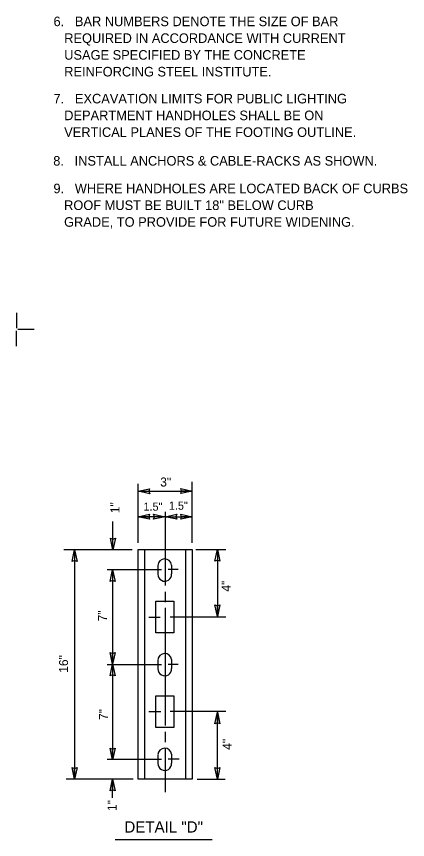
# Model space of a CAD drawing. Extents: x 19188 to 19495, y 20866 to 21061.
# Drawn here: x 19246.2 to 19280.4, y 20889.5 to 20961.5 of the extents above; entities that cross this region are included whole.
import ezdxf

# ---------------------------------------------------------------- set-up
doc = ezdxf.new("R2010")
doc.units = 0
doc.layers.add('G-ANNO-NOTE', color=7, linetype='Continuous')

msp = doc.modelspace()

# ---------------------------------------------------------------- linework, layer by layer
at = {"layer": 'G-ANNO-NOTE'}
for p, q in [((19246.175, 20935.559), (19246.175, 20934.208)), ((19246.175, 20935.559), (19246.175, 20934.208)), ((19246.175, 20932.625), (19246.175, 20933.971)), ((19246.175, 20932.625), (19246.175, 20933.971)), ((19247.715, 20934.094), (19246.305, 20934.094)), ((19247.715, 20934.094), (19246.305, 20934.094)), ((19261.529, 20915.424), (19261.529, 20920.761)), ((19256.799, 20915.424), (19256.799, 20920.584)), ((19256.799, 20919.942), (19261.546, 20919.942)), ((19256.799, 20919.942), (19257.735, 20919.942)), ((19261.546, 20919.942), (19260.61, 20919.942)), ((19254.602, 20914.807), (19254.602, 20917.298)), ((19259.164, 20917.708), (19256.793, 20917.708)), ((19256.793, 20917.708), (19257.729, 20917.708)), ((19259.164, 20917.708), (19258.228, 20917.708)), ((19259.164, 20917.708), (19261.546, 20917.708)), ((19259.164, 20917.708), (19260.1, 20917.708)), ((19261.546, 20917.708), (19260.61, 20917.708)), ((19254.602, 20914.807), (19254.602, 20915.743)), ((19256.296, 20914.807), (19250.307, 20914.807)), ((19251.258, 20914.807), (19251.258, 20894.757)), ((19251.258, 20914.807), (19251.258, 20913.87)), ((19256.799, 20914.833), (19261.529, 20914.833)), ((19256.799, 20894.757), (19256.799, 20914.833)), ((19257.39, 20894.757), (19257.39, 20914.833)), ((19260.938, 20914.833), (19260.938, 20894.757)), ((19261.529, 20914.833), (19261.529, 20894.757)), ((19261.856, 20914.839), (19264.487, 20914.839)), ((19263.74, 20914.839), (19263.74, 20908.99)), ((19263.74, 20914.839), (19263.74, 20913.903)), ((19254.101, 20913.097), (19258.841, 20913.098)), ((19254.58, 20913.073), (19254.581, 20904.805)), ((19254.58, 20913.073), (19254.581, 20912.137)), ((19258.539, 20913.446), (19258.539, 20912.658)), ((19260.303, 20913.098), (19259.437, 20913.098)), ((19259.721, 20913.482), (19259.721, 20912.713)), ((19258.361, 20910.314), (19259.938, 20910.314)), ((19258.361, 20907.555), (19258.361, 20910.314)), ((19259.938, 20910.314), (19259.938, 20907.555)), ((19263.74, 20908.99), (19263.74, 20909.926)), ((19257.746, 20908.934), (19258.733, 20908.934)), ((19264.487, 20908.935), (19259.6, 20908.934)), ((19259.938, 20907.555), (19258.361, 20907.555)), ((19254.581, 20904.805), (19254.581, 20905.742)), ((19258.539, 20905.169), (19258.539, 20904.38)), ((19259.721, 20905.205), (19259.721, 20904.436)), ((19254.102, 20904.775), (19258.841, 20904.775)), ((19254.581, 20904.805), (19254.582, 20896.437)), ((19254.581, 20904.805), (19254.581, 20903.869)), ((19260.304, 20904.775), (19259.437, 20904.775)), ((19258.361, 20902.037), (19259.938, 20902.037)), ((19258.361, 20899.277), (19258.361, 20902.037)), ((19259.938, 20902.037), (19259.938, 20899.277)), ((19257.747, 20900.657), (19258.787, 20900.657)), ((19264.488, 20900.657), (19259.6, 20900.657)), ((19263.74, 20900.621), (19263.74, 20899.685)), ((19263.74, 20894.757), (19263.74, 20900.621)), ((19259.938, 20899.277), (19258.361, 20899.277)), ((19254.582, 20896.437), (19254.582, 20897.373)), ((19254.102, 20896.497), (19258.841, 20896.497)), ((19258.539, 20896.891), (19258.539, 20896.103)), ((19260.409, 20896.497), (19259.437, 20896.497)), ((19259.721, 20896.927), (19259.721, 20896.158)), ((19251.258, 20894.757), (19251.258, 20895.693)), ((19263.74, 20894.757), (19263.74, 20895.693)), ((19256.387, 20894.749), (19250.519, 20894.749)), ((19254.582, 20893.11), (19254.582, 20894.749)), ((19254.582, 20894.749), (19254.582, 20893.813)), ((19261.529, 20894.757), (19256.799, 20894.757)), ((19261.969, 20894.749), (19264.419, 20894.749)), ((19254.787, 20889.468), (19263.277, 20889.468))]:
    msp.add_line(p, q, dxfattribs=at)
for points in [[(19257.735, 20919.942), (19257.817, 20919.718), (19256.799, 20919.942), (19257.815, 20920.156), (19257.735, 20919.942)], [(19260.61, 20919.942), (19260.528, 20920.166), (19261.546, 20919.942), (19260.53, 20919.728), (19260.61, 20919.942)], [(19257.73, 20917.708), (19257.811, 20917.484), (19256.793, 20917.708), (19257.809, 20917.922), (19257.73, 20917.708)], [(19258.227, 20917.708), (19258.145, 20917.932), (19259.164, 20917.708), (19258.148, 20917.494), (19258.227, 20917.708)], [(19259.164, 20918.126), (19259.164, 20911.687)], [(19260.1, 20917.708), (19260.182, 20917.484), (19259.164, 20917.708), (19260.18, 20917.922), (19260.1, 20917.708)], [(19260.61, 20917.708), (19260.528, 20917.932), (19261.546, 20917.708), (19260.53, 20917.494), (19260.61, 20917.708)], [(19254.602, 20915.743), (19254.826, 20915.825), (19254.602, 20914.807), (19254.389, 20915.823), (19254.602, 20915.743)], [(19251.259, 20913.87), (19251.034, 20913.788), (19251.258, 20914.807), (19251.472, 20913.791), (19251.259, 20913.87)], [(19263.74, 20913.903), (19263.517, 20913.821), (19263.74, 20914.839), (19263.954, 20913.823), (19263.74, 20913.903)], [(19254.581, 20912.137), (19254.357, 20912.055), (19254.58, 20913.073), (19254.795, 20912.057), (19254.581, 20912.137)], [(19259.164, 20911.131), (19259.164, 20910.242)], [(19263.74, 20909.926), (19263.964, 20910.008), (19263.74, 20908.99), (19263.526, 20910.006), (19263.74, 20909.926)], [(19259.164, 20909.753), (19259.164, 20905.873)], [(19254.581, 20905.742), (19254.805, 20905.824), (19254.581, 20904.805), (19254.368, 20905.822), (19254.581, 20905.742)], [(19259.164, 20905.873), (19259.164, 20899.433)], [(19254.581, 20903.869), (19254.358, 20903.787), (19254.581, 20904.805), (19254.795, 20903.789), (19254.581, 20903.869)], [(19263.74, 20899.685), (19263.517, 20899.603), (19263.74, 20900.621), (19263.954, 20899.605), (19263.74, 20899.685)], [(19259.164, 20898.878), (19259.164, 20897.989)], [(19254.582, 20897.373), (19254.805, 20897.455), (19254.582, 20896.437), (19254.368, 20897.453), (19254.582, 20897.373)], [(19259.164, 20897.5), (19259.164, 20893.62)], [(19251.258, 20895.693), (19251.482, 20895.775), (19251.258, 20894.757), (19251.044, 20895.773), (19251.258, 20895.693)], [(19263.74, 20895.693), (19263.964, 20895.775), (19263.74, 20894.757), (19263.526, 20895.773), (19263.74, 20895.693)], [(19254.582, 20893.813), (19254.359, 20893.731), (19254.582, 20894.749), (19254.796, 20893.733), (19254.582, 20893.813)]]:
    msp.add_lwpolyline(points, dxfattribs=at)
for centre, start, end in [((19259.132, 20913.428), 5.26697, 177.61228), ((19259.132, 20912.659), 177.67207, 5.26697), ((19259.132, 20905.151), 5.26697, 177.61228), ((19259.132, 20904.382), 177.67207, 5.26697), ((19259.132, 20896.873), 5.26697, 177.61228), ((19259.132, 20896.104), 177.67207, 5.26697)]:
    msp.add_arc(centre, 0.591, start, end, dxfattribs=at)

# ---------------------------------------------------------------- texts
for s, height, p in [('6.   BAR NUMBERS DENOTE THE SIZE OF BAR', 0.83785, (19249.414, 20960.627)), ('   REQUIRED IN ACCORDANCE WITH CURRENT', 0.83785, (19249.414, 20959.16)), ('   USAGE SPECIFIED BY THE CONCRETE', 0.83785, (19249.414, 20957.694)), ('   REINFORCING STEEL INSTITUTE.', 0.83785, (19249.414, 20956.228)), ('7.   EXCAVATION LIMITS FOR PUBLIC LIGHTING', 0.83785, (19249.414, 20953.87)), ('   DEPARTMENT HANDHOLES SHALL BE ON', 0.83785, (19249.414, 20952.404)), ('   VERTICAL PLANES OF THE FOOTING OUTLINE.', 0.83785, (19249.414, 20950.938)), ('8.   INSTALL ANCHORS & CABLE-RACKS AS SHOWN.', 0.83786, (19249.389, 20948.429)), ('9.   WHERE HANDHOLES ARE LOCATED BACK OF CURBS', 0.83785, (19249.404, 20946.012)), ('   ROOF MUST BE BUILT 18" BELOW CURB ', 0.83785, (19249.404, 20944.545)), ('   GRADE, TO PROVIDE FOR FUTURE WIDENING.', 0.83785, (19249.404, 20943.079)), ('3"', 0.7883, (19258.738, 20920.351)), ('1.5"', 0.7095, (19257.275, 20918.237)), ('1.5"', 0.7095, (19259.494, 20918.323)), ('DETAIL "D"', 0.9854, (19255.609, 20890.077))]:
    msp.add_text(s, height=height, dxfattribs=at).set_placement(p)
for s, p in [('1"', (19255.179, 20918.015)), ('4"', (19264.894, 20911.153)), ('7"', (19254.084, 20908.552)), ('16"', (19250.683, 20904.055)), ('7"', (19254.169, 20899.927)), ('4"', (19264.98, 20897.318)), ('1"', (19254.923, 20891.968))]:
    msp.add_text(s, height=0.7883, rotation=90, dxfattribs=at).set_placement(p)

doc.saveas('drawing.dxf')
